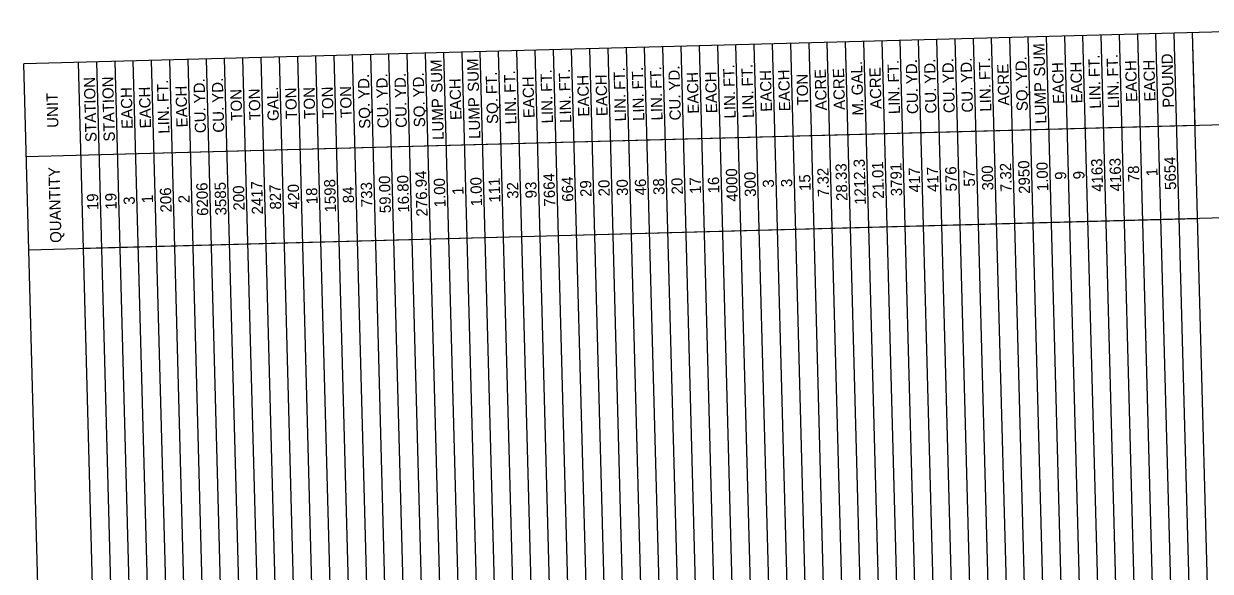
# Model space of a CAD drawing. Extents: x 1930078 to 1931323, y 596452 to 607874.
# Drawn here: x 1930081 to 1930714, y 607145 to 607438 of the extents above; entities that cross this region are included whole.
import ezdxf

# ---------------------------------------------------------------- set-up
doc = ezdxf.new("R2010")
doc.units = 0
doc.layers.add('Default', color=7, linetype='Continuous')

msp = doc.modelspace()

# ---------------------------------------------------------------- linework, layer by layer
at = {"layer": 'Default'}
for p, q in [((1930880.81, 607437.54), (1930080.62, 607416.06)), ((1930702.86, 606763.18), (1930684.9, 607432.28)), ((1930712.61, 606763.45), (1930694.65, 607432.54)), ((1930722.36, 606763.71), (1930704.4, 607432.8)), ((1930705.73, 607383.1), (1930704.4, 607432.8)), ((1930468.95, 606756.9), (1930450.99, 607426)), ((1930478.69, 606757.17), (1930460.73, 607426.26)), ((1930488.44, 606757.43), (1930470.48, 607426.52)), ((1930498.19, 606757.69), (1930480.23, 607426.79)), ((1930507.93, 606757.95), (1930489.97, 607427.05)), ((1930517.68, 606758.21), (1930499.72, 607427.31)), ((1930527.43, 606758.47), (1930509.47, 607427.57)), ((1930537.17, 606758.74), (1930519.21, 607427.83)), ((1930546.92, 606759), (1930528.96, 607428.09)), ((1930556.67, 606759.26), (1930538.71, 607428.36)), ((1930566.41, 606759.52), (1930548.45, 607428.62)), ((1930576.16, 606759.78), (1930558.2, 607428.88)), ((1930585.91, 606760.04), (1930567.94, 607429.14)), ((1930595.65, 606760.31), (1930577.69, 607429.4)), ((1930605.4, 606760.57), (1930587.44, 607429.66)), ((1930615.15, 606760.83), (1930597.18, 607429.93)), ((1930624.89, 606761.09), (1930606.93, 607430.19)), ((1930634.64, 606761.35), (1930616.68, 607430.45)), ((1930644.38, 606761.61), (1930626.42, 607430.71)), ((1930654.13, 606761.88), (1930636.17, 607430.97)), ((1930663.88, 606762.14), (1930645.92, 607431.23)), ((1930673.62, 606762.4), (1930655.66, 607431.5)), ((1930683.37, 606762.66), (1930665.41, 607431.76)), ((1930693.12, 606762.92), (1930675.16, 607432.02)), ((1930235.03, 606750.63), (1930217.07, 607419.72)), ((1930244.78, 606750.89), (1930226.82, 607419.98)), ((1930254.53, 606751.15), (1930236.56, 607420.24)), ((1930264.27, 606751.41), (1930246.31, 607420.51)), ((1930274.02, 606751.67), (1930256.06, 607420.77)), ((1930283.76, 606751.93), (1930265.8, 607421.03)), ((1930293.51, 606752.19), (1930275.55, 607421.29)), ((1930303.26, 606752.46), (1930285.3, 607421.55)), ((1930313, 606752.72), (1930295.04, 607421.81)), ((1930322.75, 606752.98), (1930304.79, 607422.08)), ((1930332.5, 606753.24), (1930314.54, 607422.34)), ((1930342.24, 606753.5), (1930324.28, 607422.6)), ((1930351.99, 606753.76), (1930334.03, 607422.86)), ((1930361.74, 606754.03), (1930343.78, 607423.12)), ((1930371.48, 606754.29), (1930353.52, 607423.38)), ((1930381.23, 606754.55), (1930363.27, 607423.65)), ((1930390.98, 606754.81), (1930373.01, 607423.91)), ((1930400.72, 606755.07), (1930382.76, 607424.17)), ((1930410.47, 606755.33), (1930392.51, 607424.43)), ((1930420.22, 606755.6), (1930402.25, 607424.69)), ((1930429.96, 606755.86), (1930412, 607424.95)), ((1930439.71, 606756.12), (1930421.75, 607425.22)), ((1930449.46, 606756.38), (1930431.49, 607425.48)), ((1930459.2, 606756.64), (1930441.24, 607425.74)), ((1930098.58, 606746.96), (1930080.62, 607416.06)), ((1930127.82, 606747.75), (1930109.86, 607416.84)), ((1930137.57, 606748.01), (1930119.61, 607417.11)), ((1930147.31, 606748.27), (1930129.35, 607417.37)), ((1930157.06, 606748.53), (1930139.1, 607417.63)), ((1930166.81, 606748.79), (1930148.85, 607417.89)), ((1930176.55, 606749.06), (1930158.59, 607418.15)), ((1930186.3, 606749.32), (1930168.34, 607418.41)), ((1930196.05, 606749.58), (1930178.09, 607418.68)), ((1930205.79, 606749.84), (1930187.83, 607418.94)), ((1930215.54, 606750.1), (1930197.58, 607419.2)), ((1930225.29, 606750.36), (1930207.32, 607419.46)), ((1930882.14, 607387.83), (1930081.95, 607366.35)), ((1930705.73, 607383.1), (1930081.95, 607366.35)), ((1930883.48, 607338.12), (1930083.29, 607316.64)), ((1930707.06, 607333.39), (1930112.53, 607317.43))]:
    msp.add_line(p, q, dxfattribs=at)

# ---------------------------------------------------------------- texts
for s, p in [(' SUM', (1930625.86, 607407.12)), (' FT.', (1930655.12, 607406.84)), (' FT.', (1930664.87, 607407.11)), ('POUND', (1930694.52, 607392.75)), (' SUM', (1930304.22, 607398.49)), (' SUM', (1930323.72, 607399.01)), (' FT.', (1930401.72, 607400.04)), (' FT.', (1930411.46, 607400.3)), (' FT.', (1930421.21, 607400.57)), (' YD.', (1930430.99, 607399.66)), (' FT.', (1930460.19, 607401.61)), (' FT.', (1930469.94, 607401.87)), ('ACRE', (1930518.99, 607391.53)), (' GAL.', (1930528.59, 607397.15)), ('ACRE', (1930538.48, 607392.05)), (' FT.', (1930547.91, 607403.97)), (' YD.', (1930557.69, 607403.06)), (' YD.', (1930567.44, 607403.32)), (' YD.', (1930577.18, 607403.58)), (' YD.', (1930586.93, 607403.85)), (' FT.', (1930596.65, 607405.28)), ('ACRE', (1930606.7, 607393.88)), (' YD.', (1930616.17, 607404.63)), ('EACH', (1930635.94, 607394.78)), ('EACH', (1930645.69, 607395.04)), ('EACH', (1930674.93, 607395.83)), ('EACH', (1930684.67, 607396.09)), ('STATION', (1930119.55, 607374.4)), ('STATION', (1930129.3, 607374.66)), (' FT.', (1930158.05, 607393.5)), (' YD.', (1930177.58, 607392.86)), (' YD.', (1930187.32, 607393.12)), (' YD.', (1930265.3, 607395.21)), (' YD.', (1930275.04, 607395.47)), (' YD.', (1930284.79, 607395.73)), (' YD.', (1930294.54, 607396)), ('EACH', (1930314.31, 607386.15)), (' FT.', (1930333.5, 607397.75)), (' FT.', (1930343.24, 607398.47)), ('EACH', (1930353.29, 607387.19)), (' FT.', (1930362.73, 607399)), (' FT.', (1930372.48, 607399.26)), ('EACH', (1930382.53, 607387.98)), ('EACH', (1930392.28, 607388.24)), ('EACH', (1930441.01, 607389.55)), ('EACH', (1930450.76, 607389.81)), ('EACH', (1930480, 607390.59)), ('EACH', (1930489.74, 607390.86)), ('TON', (1930499.41, 607393.92)), ('ACRE', (1930509.24, 607391.27)), ('EACH', (1930138.87, 607381.44)), ('EACH', (1930148.62, 607381.7)), ('EACH', (1930168.11, 607382.22)), ('TON', (1930197.27, 607385.81)), ('TON', (1930207.02, 607386.07)), ('GAL.', (1930216.79, 607385.65)), ('TON', (1930226.51, 607386.59)), ('TON', (1930236.26, 607386.86)), ('TON', (1930246.01, 607387.12)), ('TON', (1930255.75, 607387.38)), ('LIN.', (1930460.59, 607386.98)), ('LIN.', (1930470.33, 607387.24)), ('LIN.', (1930548.31, 607389.33)), ('CU.', (1930558.06, 607389.36)), ('CU.', (1930567.8, 607389.62)), ('CU.', (1930577.55, 607389.88)), ('CU.', (1930587.3, 607390.14)), ('LIN.', (1930597.04, 607390.64)), ('SQ.', (1930616.54, 607390.93)), ('LUMP', (1930626.47, 607384.21)), ('LIN.', (1930655.52, 607392.21)), ('LIN.', (1930665.26, 607392.47)), ('UNIT', (1930099.17, 607381.99)), ('SQ.', (1930265.66, 607381.51)), ('CU.', (1930275.41, 607381.77)), ('CU.', (1930285.16, 607382.03)), ('SQ.', (1930294.9, 607382.29)), ('LUMP', (1930304.84, 607375.57)), ('LUMP', (1930324.33, 607376.1)), ('SQ.', (1930333.87, 607384.04)), ('LIN.', (1930343.63, 607383.84)), ('LIN.', (1930363.12, 607384.36)), ('LIN.', (1930372.87, 607384.62)), ('LIN.', (1930402.11, 607385.41)), ('LIN.', (1930411.85, 607385.67)), ('LIN.', (1930421.6, 607385.93)), ('CU.', (1930431.35, 607385.96)), ('M.', (1930528.82, 607388.57)), ('LIN.', (1930158.45, 607378.87)), ('CU.', (1930177.95, 607379.16)), ('CU.', (1930187.69, 607379.42)), ('28.33', (1930520.29, 607342.95)), ('1212.3', (1930530.1, 607340.88)), ('21.01', (1930539.77, 607344.05)), ('3791', (1930549.48, 607345.48)), ('7.32', (1930607.95, 607347.66)), ('2950', (1930617.72, 607346.74)), ('1.00', (1930627.44, 607348.17)), ('4163', (1930656.71, 607347.78)), ('4163', (1930666.46, 607348.04)), ('5654', (1930695.7, 607348.84)), ('QUANTITY', (1930100.82, 607320.55)), ('16.80', (1930286.37, 607336.68)), ('276.94', (1930296.18, 607334.62)), ('7664', (1930364.31, 607339.94)), ('4000', (1930461.78, 607342.55)), ('300', (1930471.46, 607345.14)), ('15', (1930500.64, 607348.22)), ('7.32', (1930510.48, 607345.05)), ('417', (1930559.18, 607347.49)), ('417', (1930568.93, 607347.75)), ('576', (1930578.68, 607348.01)), ('57', (1930588.36, 607350.6)), ('300', (1930598.17, 607348.55)), ('9', (1930637.03, 607354.24)), ('9', (1930646.78, 607354.5)), ('78', (1930676.08, 607352.95)), ('1', (1930685.75, 607356.13)), ('6206', (1930179.13, 607334.96)), ('3585', (1930188.88, 607335.19)), ('200', (1930198.56, 607337.82)), ('2417', (1930208.37, 607335.74)), ('827', (1930218.06, 607338.33)), ('420', (1930227.8, 607338.6)), ('1598', (1930247.36, 607336.78)), ('84', (1930256.98, 607341.72)), ('733', (1930266.79, 607339.64)), ('59.00', (1930276.63, 607336.42)), ('1.00', (1930305.8, 607339.53)), ('1', (1930315.38, 607346.19)), ('1.00', (1930325.3, 607340.06)), ('111', (1930335, 607342.05)), ('32', (1930344.7, 607344.09)), ('93', (1930354.44, 607344.32)), ('664', (1930374, 607342.53)), ('29', (1930383.68, 607345.1)), ('20', (1930393.43, 607345.38)), ('30', (1930403.18, 607345.64)), ('46', (1930412.92, 607345.89)), ('38', (1930422.67, 607346.15)), ('20', (1930432.42, 607346.43)), ('17', (1930442.16, 607346.68)), ('16', (1930451.91, 607346.94)), ('3', (1930481.09, 607350.05)), ('3', (1930490.83, 607350.32)), ('19', (1930120.53, 607338.04)), ('19', (1930130.27, 607338.3)), ('3', (1930139.96, 607340.9)), ('1', (1930149.69, 607341.74)), ('206', (1930159.58, 607336.76)), ('2', (1930169.2, 607341.71)), ('18', (1930237.49, 607341.18))]:
    msp.add_text(s, height=6, rotation=91.53769, dxfattribs=at).set_placement(p)

doc.saveas('drawing.dxf')
